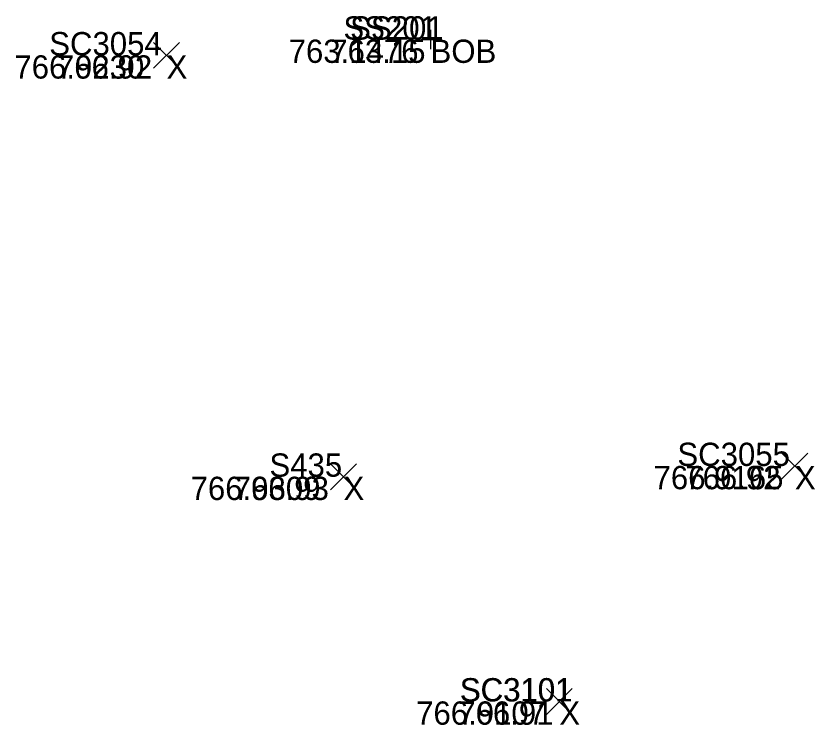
# Model space of a CAD drawing. Extents: x 1845019 to 1877956, y 680444 to 701081.
# Drawn here: x 1857790.489 to 1857792.547, y 694212.604 to 694214.432 of the extents above; entities that cross this region are included whole.
import ezdxf

# ---------------------------------------------------------------- set-up
doc = ezdxf.new("R2010")
doc.units = 0
for name, color, linetype in [('BR_X_SV_Bottom_of_Beam_Text', 7, 'Continuous'), ('SV_X_Random_Point', 7, 'Continuous'), ('SV_X_Text_Comment', 7, 'Continuous'), ('SV_X_Text_Elevation', 7, 'Continuous'), ('SV_X_Text_Name', 7, 'Continuous')]:
    doc.layers.add(name, color=color, linetype=linetype)

msp = doc.modelspace()

# ---------------------------------------------------------------- linework, layer by layer
at = {"layer": 'BR_X_SV_Bottom_of_Beam_Text'}
for p, q in [((1857791.5567, 694214.3958), (1857791.5567, 694214.3458)), ((1857791.5567, 694214.3958), (1857791.5567, 694214.3458)), ((1857791.5317, 694214.3708), (1857791.5817, 694214.3708)), ((1857791.5317, 694214.3708), (1857791.5817, 694214.3708)), ((1857791.5567, 694214.3708), (1857791.5567, 694214.3708)), ((1857791.5567, 694214.3708), (1857791.5567, 694214.3708))]:
    msp.add_line(p, q, dxfattribs=at)
at = {"layer": 'SV_X_Random_Point'}
for p, q in [((1857790.8432, 694214.2969), (1857790.9098, 694214.3637)), ((1857790.8432, 694214.3637), (1857790.9098, 694214.2969)), ((1857790.8432, 694214.2969), (1857790.9098, 694214.3637)), ((1857790.8432, 694214.3637), (1857790.9098, 694214.2969)), ((1857792.4622, 694213.2384), (1857792.5288, 694213.3052)), ((1857792.4622, 694213.3052), (1857792.5288, 694213.2384)), ((1857792.4622, 694213.2384), (1857792.5288, 694213.3052)), ((1857792.4622, 694213.3052), (1857792.5288, 694213.2384)), ((1857791.2991, 694213.2107), (1857791.3657, 694213.2775)), ((1857791.2991, 694213.2775), (1857791.3657, 694213.2107)), ((1857791.2991, 694213.2107), (1857791.3657, 694213.2775)), ((1857791.2991, 694213.2775), (1857791.3657, 694213.2107)), ((1857791.8552, 694212.6315), (1857791.9218, 694212.6983)), ((1857791.8552, 694212.6983), (1857791.9218, 694212.6315)), ((1857791.8552, 694212.6315), (1857791.9218, 694212.6983)), ((1857791.8552, 694212.6983), (1857791.9218, 694212.6315))]:
    msp.add_line(p, q, dxfattribs=at)

# ---------------------------------------------------------------- texts
at = {"layer": 'BR_X_SV_Bottom_of_Beam_Text'}
for s, p in [('SS201', (1857791.3322, 694214.3708)), ('SS201', (1857791.3496, 694214.3708)), ('763.1476', (1857791.1911, 694214.3108)), ('763.15', (1857791.2983, 694214.3108)), ('BOB', (1857791.5567, 694214.3108))]:
    msp.add_text(s, height=0.06, dxfattribs=at).set_placement(p)
at = {"layer": 'SV_X_Text_Comment'}
for p in [(1857790.8765, 694214.2703), (1857792.4955, 694213.2118), (1857791.3324, 694213.1841), (1857791.8885, 694212.6049)]:
    msp.add_text('X', height=0.06, dxfattribs=at).set_placement(p)
at = {"layer": 'SV_X_Text_Elevation'}
for s, p in [('766.9230', (1857790.4844, 694214.2703)), ('766.92', (1857790.594, 694214.2703)), ('766.9165', (1857792.1313, 694213.2118)), ('766.92', (1857792.213, 694213.2118)), ('766.9309', (1857790.9384, 694213.1841)), ('766.93', (1857791.0494, 694213.1841)), ('766.9107', (1857791.5196, 694212.6049)), ('766.91', (1857791.6281, 694212.6049))]:
    msp.add_text(s, height=0.06, dxfattribs=at).set_placement(p)
at = {"layer": 'SV_X_Text_Name'}
for s, p in [('SC3054', (1857790.5742, 694214.3303)), ('SC3054', (1857790.5742, 694214.3303)), ('SC3055', (1857792.1927, 694213.2718)), ('SC3055', (1857792.1927, 694213.2718)), ('S435', (1857791.1416, 694213.2441)), ('S435', (1857791.1416, 694213.2441)), ('SC3101', (1857791.6319, 694212.6649)), ('SC3101', (1857791.6328, 694212.6649))]:
    msp.add_text(s, height=0.06, dxfattribs=at).set_placement(p)

doc.saveas('drawing.dxf')
